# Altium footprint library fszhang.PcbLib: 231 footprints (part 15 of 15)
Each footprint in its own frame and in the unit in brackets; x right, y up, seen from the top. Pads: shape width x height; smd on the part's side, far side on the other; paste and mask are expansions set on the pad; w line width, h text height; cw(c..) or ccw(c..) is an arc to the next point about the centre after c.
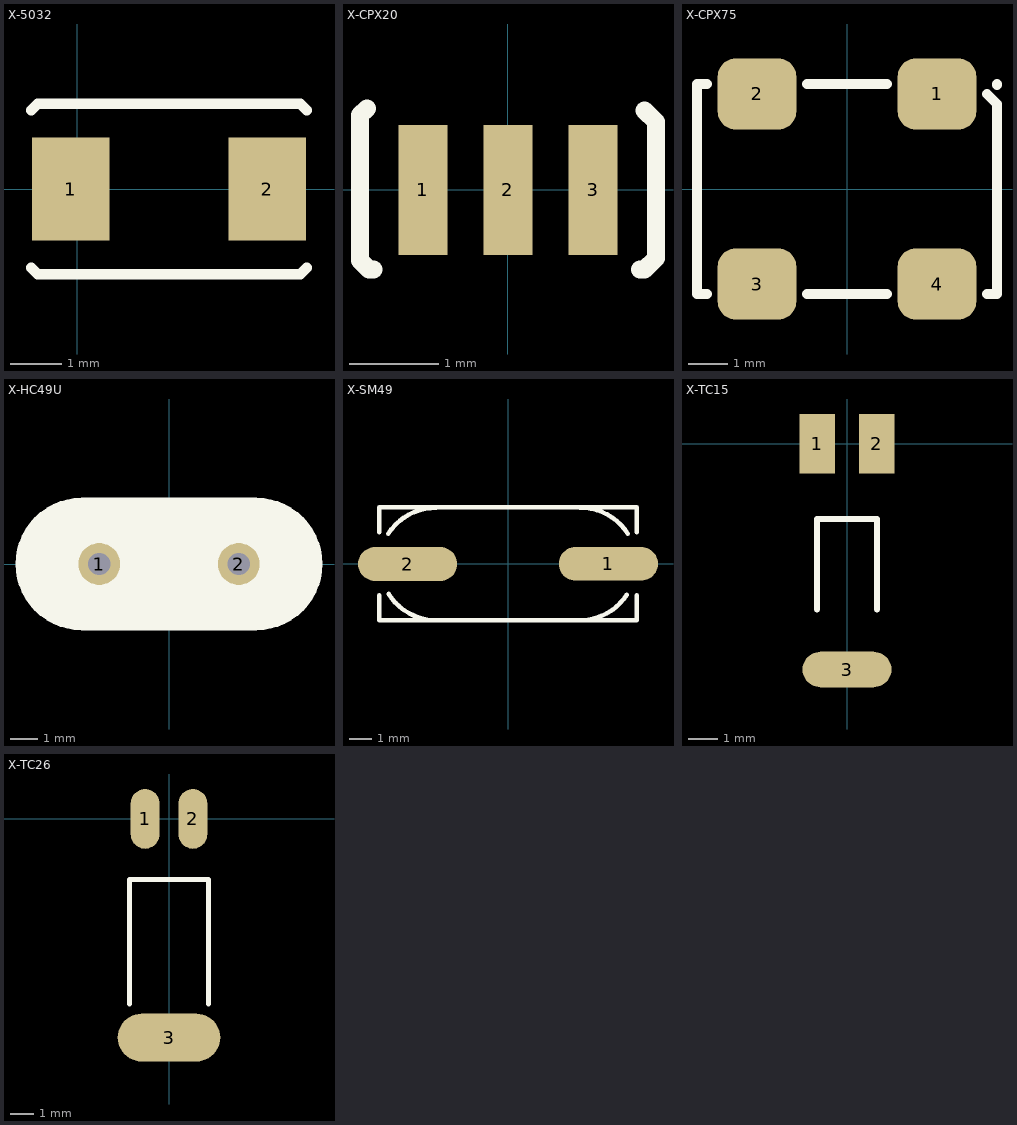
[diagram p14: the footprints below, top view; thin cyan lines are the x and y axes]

## X-5032 [mm]
pads (2):
  rect 1.5x2 smd: 1(-0.127,0) 2(3.683,0)
Top Overlay:
  lines w0.2: -0.889,-1.524 -0.762,-1.651 4.318,-1.651 4.445,-1.524 ; -0.889,1.524 -0.762,1.651 4.318,1.651 4.445,1.524

## X-CPX20 [mm] "贴片晶振"
pads (3):
  rect 0.55x1.45 smd: 1(-0.95,0) 2(0,0) 3(0.95,0)
Top Overlay:
  lines w0.2: -1.576,0.911 -1.651,0.836 -1.651,-0.789 -1.551,-0.889 -1.501,-0.889 ; 1.474,-0.889 1.524,-0.889 1.651,-0.762 1.651,0.762 1.524,0.889

## X-CPX75 [mm]
height 14.8
pads (4):
  rrect50% 2x1.8 smd: 1(2.281,2.415) 2(-2.291,2.415) 3(-2.291,-2.411) 4(2.281,-2.411)
Top Overlay:
  lines w0.254: -3.561,-2.665 -3.815,-2.665 -3.815,2.669 -3.561,2.669 ; -1.021,-2.665 1.011,-2.665 ; -1.021,2.669 1.011,2.669 ; 3.551,-2.665 3.805,-2.665 3.805,2.161 3.551,2.415 ; 3.805,2.644 3.805,2.669

## X-HC49U [mil] "插件晶振"
height 157.48
pads (2):
  round 60 hole 32: 1(-100,0) 2(100,0)
Top Overlay:
  lines w10: -125,-90 cw(c-125,0) -125,90 125,90 cw(c125,0) 125,-90 -125,-90
  lines w177.17: -125,0 125,0

## X-SM49 [mm]
height 14.8
pads (2):
  oval 4.4x1.5 smd: 1(4.45,0.004) 2(-4.45,-0.004)
Top Overlay:
  lines w0.2: -5.7,-2.499 5.718,-2.499 ; -5.7,-2.496 -5.7,-1.397 ; -5.7,1.397 -5.7,2.504 5.718,2.504 5.718,1.397 ; -5.307,1.334 cw(c-3.202,-0.013) -3.175,2.487 ; -5.296,-1.326 ccw(c-3.176,-0.001) -3.176,-2.501 ; 3.175,-2.5 ccw(c3.175,0) 5.274,-1.358 ; 3.175,2.496 cw(c3.202,-0.004) 5.312,1.336 ; 5.718,-2.496 5.718,-1.397

## X-TC15 [mm] "圆柱晶振1"
pads (3):
  rect 1.2x2 smd: 1(-1,0) 2(1,0)
  oval 3x1.2 smd: 3(0,-7.62)
Top Overlay:
  lines w0.2: -1.016,-5.588 -1.016,-2.54 1.016,-2.54 1.016,-5.588
3D body: height 1.99, standoff 0, extent -0.998,-8.286 0.998,-2.286
3D body: height 1.1, standoff 0.9, extent -0.735,-3 -0.535,0
3D body: height 1.1, standoff 0.9, extent 0.535,-3 0.735,0

## X-TC26 [mm] "圆柱晶振2"
pads (3):
  oval 1.2x2.5 smd: 1(-1,0) 2(1,0)
  oval 4.3x2 smd: 3(0,-9.144)
Top Overlay:
  lines w0.2: -1.651,-7.747 -1.651,-2.54 1.651,-2.54 1.651,-7.747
